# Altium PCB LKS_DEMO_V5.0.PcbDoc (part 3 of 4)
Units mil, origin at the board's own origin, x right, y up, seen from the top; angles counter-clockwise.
Board outline 5414.8 x 3354.56 mil, 2 copper layers (Top Layer, Bottom Layer); 131 components, 85 nets, 355 pads, 272 vias.
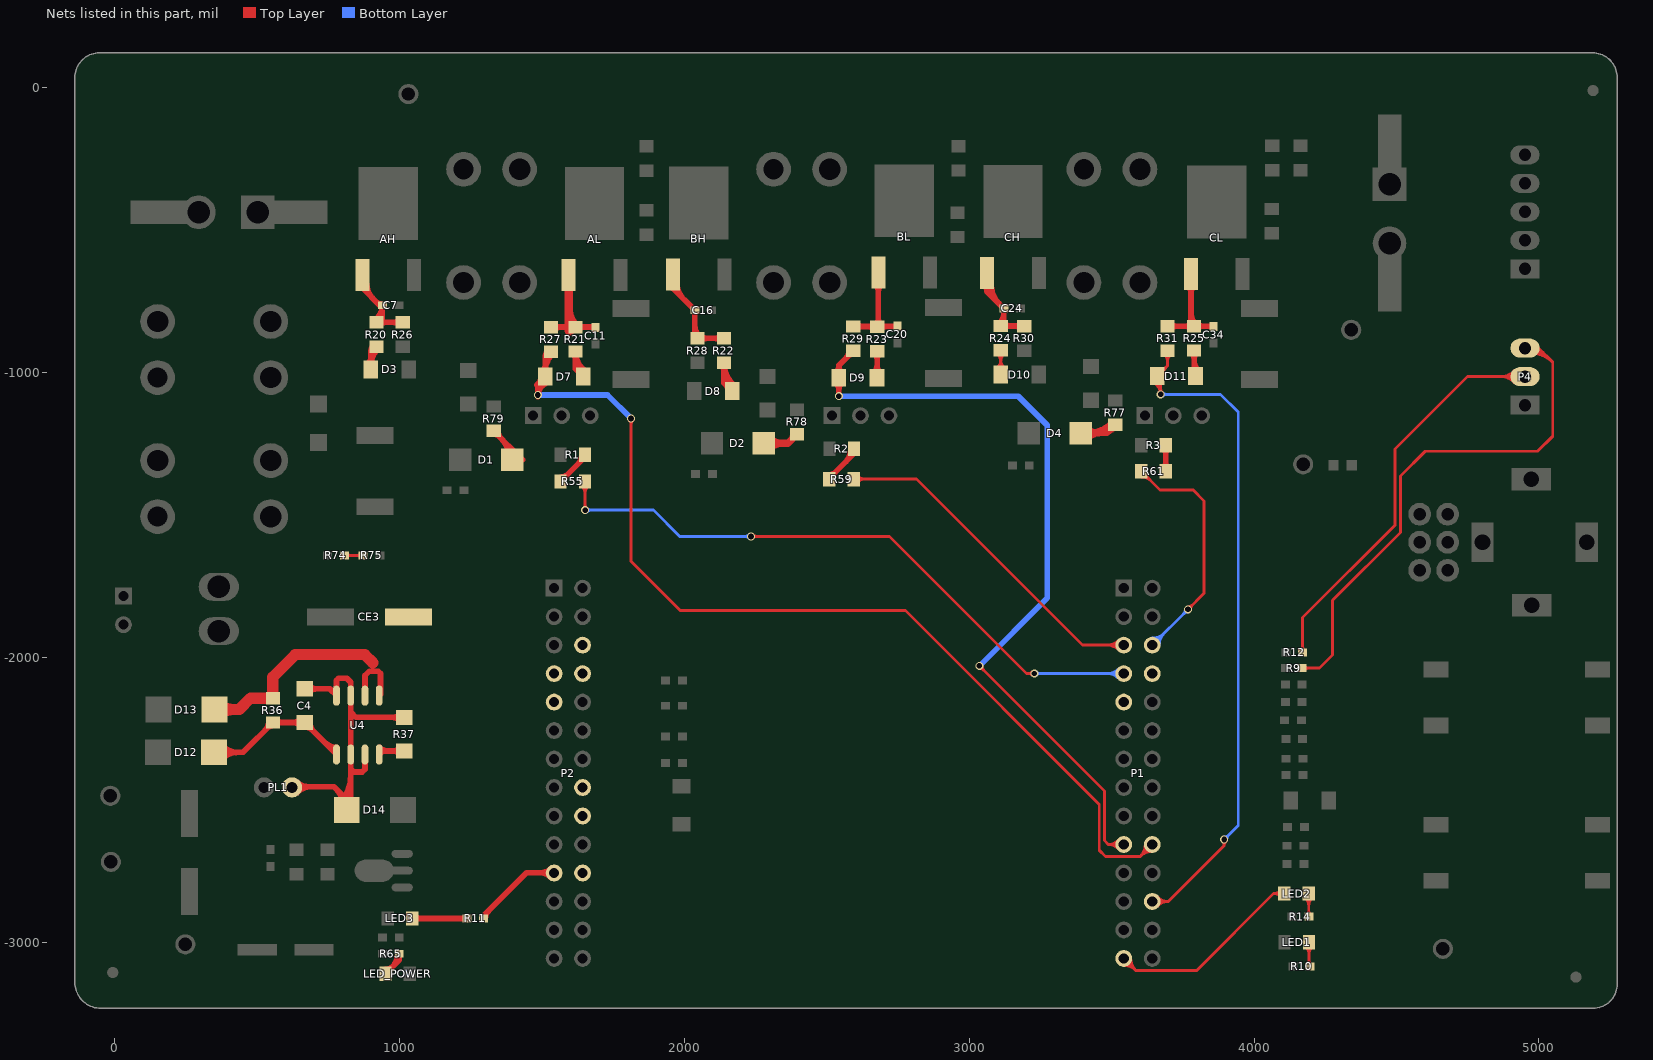
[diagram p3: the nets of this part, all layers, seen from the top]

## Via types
v1: diameter 26, hole 18, Top Layer to Bottom Layer, 117 vias
v2: diameter 28, hole 20, Top Layer to Bottom Layer, 77 vias
v3: diameter 28, hole 18, Top Layer to Bottom Layer, 73 vias
v4: diameter 23.62, hole 11.81, Top Layer to Bottom Layer, 5 vias

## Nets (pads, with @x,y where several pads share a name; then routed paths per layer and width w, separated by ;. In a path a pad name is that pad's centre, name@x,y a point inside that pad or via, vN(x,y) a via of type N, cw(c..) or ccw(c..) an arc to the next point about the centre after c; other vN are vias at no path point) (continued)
LED2: LED2.1 P1.14 | length 1103.3
  Top Layer w10: P1.14@3542.25,-3056.82 3584.65,-3099.22 3798.25,-3099.22 4068.35,-2829.12 ; LED2.1@4105.98,-2829.12 4068.35,-2829.12 ; 3567.05,-3081.62 ccw(c3542.25,-3106.42) 3542.25,-3071.34 cw(c3542.25,-3106.42) 3567.05,-3081.62 ; 3567.05,-3081.62 cw(c3591.85,-3056.82) 3556.78,-3056.82 ccw(c3591.85,-3056.82) 3567.05,-3081.62 ; 3584.12,-3098.69 ccw(c3542.25,-3140.56) 3542.25,-3081.34 cw(c3542.25,-3140.56) 3584.12,-3098.69 ; 3584.12,-3098.69 cw(c3625.99,-3056.82) 3566.78,-3056.82 ccw(c3625.99,-3056.82) 3584.12,-3098.69 ; 4068.35,-2829.12 ccw(c4068.35,-2794.93) 4093.65,-2817.92 cw(c4068.35,-2794.93) 4068.35,-2829.12 ; 4068.35,-2829.12 cw(c4068.35,-2863.3) 4093.65,-2840.31 ccw(c4068.35,-2863.3) 4068.35,-2829.12
LED3: P2.11 R11.2 | length 526.2
  Top Layer w20: R11.2@1295.18,-2916.6 1295.18,-2906.6 1446.24,-2755.53 P2.11@1540.97,-2755.53 ; R11.2@1300.93,-2916.6 cw(c1338.95,-2916.6) 1312.06,-2889.71 ccw(c1338.95,-2916.6) R11.2@1300.93,-2916.6 ; 1492.01,-2755.53 cw(c1492.01,-2807.06) 1528.44,-2770.62 ccw(c1492.01,-2807.06) 1492.01,-2755.53 ; 1498.2,-2755.53 ccw(c1498.2,-2712.77) 1528.44,-2743.01 cw(c1498.2,-2712.77) 1498.2,-2755.53
LO1: D11.2 P1.26 R31.1 | length 3359.8
  Top Layer w10: P1.26@3642.25,-2856.82 3698.24,-2856.82 ; v2(3671.64,-1076.41) 3671.63,-1023.64 D11.2@3660.13,-1012.14 3696.16,-976.11 ; R31.1@3696.16,-923.03 3696.16,-976.11 ; v2(3894.93,-2639.57) 3894.93,-2660.12 ; 3671.63,-1054.66 ccw(c3693.39,-1054.66) 3678,-1070.04 cw(c3693.39,-1054.66) 3671.63,-1054.66 ; 3671.63,-1054.7 cw(c3649.93,-1054.7) 3665.28,-1070.04 ccw(c3649.93,-1054.7) 3671.63,-1054.7 ; 3675.41,-2856.82 ccw(c3675.41,-2887.4) 3652.93,-2866.66 cw(c3675.41,-2887.4) 3675.41,-2856.82 ; 3675.41,-2856.82 cw(c3675.41,-2826.23) 3652.93,-2846.97 ccw(c3675.41,-2826.23) 3675.41,-2856.82 ; 3696.16,-976.11 cw(c3670.73,-950.68) 3663.99,-986.01 ccw(c3670.73,-950.68) 3696.16,-976.11 ; 3696.16,-963.23 ccw(c3655.95,-963.23) 3684.38,-934.8 cw(c3655.95,-963.23) 3696.16,-963.23 ; 3696.16,-963.23 cw(c3736.37,-963.23) 3707.94,-934.8 ccw(c3736.37,-963.23) 3696.16,-963.23 ; 3698.24,-2856.82 ccw(c3698.24,-2908.45) 3660.28,-2873.44 cw(c3698.24,-2908.45) 3698.24,-2856.82 ; 3698.24,-2856.82 cw(c3698.24,-2805.18) 3660.28,-2840.19 ccw(c3698.24,-2805.18) 3698.24,-2856.82 ; 3698.24,-2856.82 3894.93,-2660.12 ; 3894.93,-2660.12 ccw(c3875.97,-2660.12) 3888.83,-2646.19 cw(c3875.97,-2660.12) 3894.93,-2660.12 ; 3894.93,-2660.12 cw(c3913.89,-2660.12) 3901.03,-2646.19 ccw(c3913.89,-2660.12) 3894.93,-2660.12 ; D11.2@3648.83,-1035.25 cw(c3621.06,-1077.52) 3671.63,-1077.52 ccw(c3621.06,-1077.52) D11.2@3648.83,-1035.25 ; D11.2@3654.32,-1026.9 cw(c3633.24,-1058.99) 3671.63,-1058.99 ccw(c3633.24,-1058.99) D11.2@3654.32,-1026.9 ; D11.2@3662.12,-995.83 ccw(c3666.45,-973.11) 3682.8,-989.47 cw(c3666.45,-973.11) D11.2@3662.12,-995.83 ; D11.2@3680.72,-1006.23 cw(c3716.17,-1006.23) 3691.11,-981.16 ccw(c3716.17,-1006.23) D11.2@3680.72,-1006.23
  Bottom Layer w10: v2(3671.64,-1076.41) 3882.12,-1076.41 3944.39,-1138.68 3944.39,-2590.11 v2(3894.93,-2639.57) ; 3693.37,-1076.41 ccw(c3693.37,-1098.14) 3678,-1082.77 cw(c3693.37,-1098.14) 3693.37,-1076.41 ; 3693.37,-1076.41 cw(c3693.37,-1054.68) 3678,-1070.04 ccw(c3693.37,-1054.68) 3693.37,-1076.41 ; 3910.29,-2624.21 ccw(c3925.66,-2639.57) 3903.93,-2639.57 cw(c3925.66,-2639.57) 3910.29,-2624.21 ; 3910.29,-2624.21 cw(c3894.93,-2608.85) 3894.93,-2630.57 ccw(c3894.93,-2608.85) 3910.29,-2624.21
LO2: D9.2 P1.10 R29.1 | length 3418.4
  Top Layer w10: v2(3035.34,-2029.67) 3474.16,-2468.49 3474.16,-2643.33 3487.65,-2656.82 ; P1.10@3542.25,-2656.82 3487.65,-2656.82 ; 3050.71,-2045.04 ccw(c3035.34,-2060.4) 3035.34,-2038.67 cw(c3035.34,-2060.4) 3050.71,-2045.04 ; 3050.71,-2045.04 cw(c3066.07,-2029.67) 3044.34,-2029.67 ccw(c3066.07,-2029.67) 3050.71,-2045.04 ; 3487.65,-2656.82 ccw(c3487.65,-2608.31) 3523.91,-2640.53 cw(c3487.65,-2608.31) 3487.65,-2656.82 ; 3487.65,-2656.82 cw(c3487.65,-2705.32) 3523.91,-2673.11 ccw(c3487.65,-2705.32) 3487.65,-2656.82 ; 3509.91,-2656.82 ccw(c3509.91,-2628.09) 3531.39,-2647.17 cw(c3509.91,-2628.09) 3509.91,-2656.82 ; 3509.91,-2656.82 cw(c3509.91,-2685.55) 3531.39,-2666.46 ccw(c3509.91,-2685.55) 3509.91,-2656.82
  Top Layer w20: v2@2542,-1080.2 D9.2@2542,-1018.22 2542,-974.29 R29.1@2592.71,-923.58 ; 2542,-1061.76 ccw(c2504.36,-1061.76) 2530.98,-1035.15 cw(c2504.36,-1061.76) 2542,-1061.76 ; 2542,-1061.76 cw(c2579.64,-1061.76) 2553.03,-1035.15 ccw(c2579.64,-1061.76) 2542,-1061.76 ; 2542,-974.67 ccw(c2579.64,-974.67) 2553.03,-1001.29 cw(c2579.64,-974.67) 2542,-974.67 ; 2542,-974.67 cw(c2504.36,-974.67) 2530.98,-1001.29 ccw(c2504.36,-974.67) 2542,-974.67 ; 2567.1,-949.19 ccw(c2541.5,-923.58) 2577.71,-923.58 cw(c2541.5,-923.58) 2567.1,-949.19 ; R29.1@2575.18,-941.11 cw(c2589.36,-955.29) 2589.36,-935.24 ccw(c2589.36,-955.29) R29.1@2575.18,-941.11
  Bottom Layer w20: v2(2541.86,-1082.8) 3171.74,-1082.8 3273.63,-1184.7 3273.63,-1791.37 v2(3035.34,-2029.67)
LO3: D7.2 P1.24 R27.1 | length 4384.4
  Top Layer w10: v2(1812.37,-1160.96) 1812.37,-1662.33 1985.23,-1835.2 2775.6,-1835.2 3456.28,-2515.88 3456.28,-2677.23 3478.27,-2699.22 3599.85,-2699.22 P1.24@3638.22,-2660.84 ; 1812.37,-1182.68 ccw(c1790.64,-1182.68) 1806,-1167.32 cw(c1790.64,-1182.68) 1812.37,-1182.68 ; 1812.37,-1182.68 cw(c1834.1,-1182.68) 1818.73,-1167.32 ccw(c1834.1,-1182.68) 1812.37,-1182.68 ; 3600.38,-2698.69 ccw(c3558.51,-2656.82) 3617.72,-2656.82 cw(c3558.51,-2656.82) 3600.38,-2698.69 ; 3600.38,-2698.69 cw(c3642.25,-2740.56) 3642.25,-2681.34 ccw(c3642.25,-2740.56) 3600.38,-2698.69 ; 3617.45,-2681.62 ccw(c3592.65,-2656.82) 3627.72,-2656.82 cw(c3592.65,-2656.82) 3617.45,-2681.62 ; 3617.45,-2681.62 cw(c3642.25,-2706.42) 3642.25,-2671.34 ccw(c3642.25,-2706.42) 3617.45,-2681.62
  Top Layer w20: v2(1485.26,-1078.73) 1485.25,-1040.35 D7.2@1511.3,-1014.31 1511.3,-946.61 R27.1@1531.29,-926.62 ; 1511.29,-970.77 ccw(c1548.93,-970.77) 1522.32,-997.38 cw(c1548.93,-970.77) 1511.29,-970.77 ; 1511.3,-970.77 cw(c1473.66,-970.77) 1500.27,-997.38 ccw(c1473.66,-970.77) 1511.3,-970.77 ; 1482.3,-1043.31 cw(c1502.52,-1063.53) 1508.2,-1035.5 ccw(c1502.52,-1063.53) 1482.3,-1043.31 ; v2@1485.25,-1084.26 cw(c1539.73,-1084.26) 1517.62,-1034.47 ccw(c1539.73,-1084.26) v2@1485.25,-1084.26 ; 1485.25,-1053.49 cw(c1526.07,-1053.49) 1509.51,-1016.19 ccw(c1526.07,-1053.49) 1485.25,-1053.49 ; D7.2@1488.86,-1036.75 ccw(c1472.32,-1020.22) 1495.7,-1020.22 cw(c1472.32,-1020.22) D7.2@1488.86,-1036.75 ; D7.2@1511.29,-994.94 cw(c1596.27,-994.94) 1536.18,-934.86 ccw(c1596.27,-994.94) D7.2@1511.29,-994.94 ; R27.1@1511.3,-946.66 cw(c1547.99,-946.66) 1522.04,-920.71 ccw(c1547.99,-946.66) R27.1@1511.3,-946.66
  Bottom Layer w20: v2(1485.26,-1078.73) 1729.95,-1078.73 v2@1811.08,-1159.86
NetAH_1: AH.1 C7.1 R20.1 R26.2 | length 811.3
  Top Layer w20: AH.1@869.01,-654.65 869.01,-702.97 929.44,-763.4 C7.1@939.25,-763.4 ; R26.2@1010.36,-823.64 R20.1@918.27,-823.64 939.25,-802.67 C7.1@939.25,-763.4 ; C7.1@939.25,-763.4 cw(c874.31,-763.41) 914.42,-814.48 ccw(c874.31,-763.41) C7.1@939.25,-763.4 ; 949.75,-823.64 ccw(c949.75,-851.78) 929.86,-831.89 cw(c949.75,-851.78) 949.75,-823.64 ; 949.75,-823.64 cw(c949.75,-795.51) 929.86,-815.4 ccw(c949.75,-795.51) 949.75,-823.64 ; AH.1@884.52,-689.66 ccw(c954.1,-689.66) 904.9,-738.86 cw(c954.1,-689.66) AH.1@884.52,-689.66 ; 917.45,-751.41 ccw(c937.28,-731.58) 937.28,-759.63 cw(c937.28,-731.58) 917.45,-751.41 ; R20.1@926.77,-830.21 ccw(c906.62,-804.55) 939.25,-804.55 cw(c906.62,-804.55) R20.1@926.77,-830.21 ; 978.65,-823.64 cw(c978.65,-852.32) 998.93,-832.04 ccw(c978.65,-852.32) 978.65,-823.64 ; 979.42,-823.64 ccw(c979.42,-796.05) 998.93,-815.56 cw(c979.42,-796.05) 979.42,-823.64
NetAL_1: AL.1 C11.1 R21.1 R27.2 | length 760.3
  Top Layer w20: R27.2@1527.25,-839.83 C11.1@1687.64,-839.83 ; R27.2@1542.88,-849.23 cw(c1565.56,-871.91) 1565.56,-839.83 ccw(c1565.56,-871.91) R27.2@1542.88,-849.23 ; R27.2@1542.88,-832.75 ccw(c1559.98,-815.64) 1559.98,-839.83 cw(c1559.98,-815.64) R27.2@1542.88,-832.75 ; 1583.7,-839.83 cw(c1583.7,-870.45) 1605.36,-848.8 ccw(c1583.7,-870.45) 1583.7,-839.83 ; 1587.22,-839.83 ccw(c1587.22,-814.19) 1605.36,-832.32 cw(c1587.22,-814.19) 1587.22,-839.83 ; R21.1@1628.53,-848.8 cw(c1650.18,-870.45) 1650.18,-839.83 ccw(c1650.18,-870.45) R21.1@1628.53,-848.8 ; R21.1@1628.53,-832.32 ccw(c1646.66,-814.19) 1646.66,-839.83 cw(c1646.66,-814.19) R21.1@1628.53,-832.32
  Top Layer w30: R21.1@1593.54,-840.56 AL.1@1593.54,-657.72 ; R21.1@1593.54,-848.49 ccw(c1605.66,-848.49) 1597.09,-857.07 cw(c1605.66,-848.49) R21.1@1593.54,-848.49 ; 1593.54,-776.07 ccw(c1678.09,-776.07) 1618.3,-835.86 cw(c1678.09,-776.07) 1593.54,-776.07
NetBH_1: BH.1 C16.1 R22.1 R28.2 | length 714.4
  Top Layer w20: BH.1@1959.82,-653.06 1959.82,-704.49 C16.1@2036.35,-781.02 R28.2@2036.35,-870 ; R28.2@2046.11,-879.76 R22.1@2138.49,-879.76 ; 2077.59,-879.76 ccw(c2077.59,-907.89) 2057.69,-888 cw(c2077.59,-907.89) 2077.59,-879.76 ; 2077.59,-879.76 cw(c2077.59,-851.62) 2057.69,-871.52 ccw(c2077.59,-851.62) 2077.59,-879.76 ; BH.1@1974.12,-687.65 ccw(c2049.28,-687.65) 1996.13,-740.8 cw(c2049.28,-687.65) BH.1@1974.12,-687.65 ; 2036.35,-836.15 ccw(c2086.37,-836.15) 2051,-871.52 cw(c2086.37,-836.15) 2036.35,-836.15 ; 2106.85,-879.76 cw(c2106.85,-908.29) 2127.02,-888.11 ccw(c2106.85,-908.29) 2106.85,-879.76 ; 2107.41,-879.76 ccw(c2107.41,-852.02) 2127.02,-871.63 cw(c2107.41,-852.02) 2107.41,-879.76
NetBL_1: BL.1 C20.1 R23.1 R29.2 | length 803.9
  Top Layer w20: R29.2@2592.71,-837.95 C20.1@2745.87,-837.95 ; R23.1@2680.58,-835.25 BL.1@2680.58,-648.88 ; 2624.19,-837.95 ccw(c2624.19,-866.09) 2604.3,-846.2 cw(c2624.19,-866.09) 2624.19,-837.95 ; 2624.19,-837.95 cw(c2624.19,-809.82) 2604.3,-829.71 ccw(c2624.19,-809.82) 2624.19,-837.95 ; 2680.58,-715.64 ccw(c2645.32,-715.64) 2670.26,-690.7 cw(c2645.32,-715.64) 2680.58,-715.64 ; 2680.58,-715.64 cw(c2715.85,-715.64) 2690.91,-690.7 ccw(c2715.85,-715.64) 2680.58,-715.64 ; R23.1@2687.91,-831.27 ccw(c2704.06,-815.13) 2704.06,-837.95 cw(c2704.06,-815.13) R23.1@2687.91,-831.27 ; R23.1@2687.91,-831.27 cw(c2705.61,-813.57) 2680.58,-813.57 ccw(c2705.61,-813.57) R23.1@2687.91,-831.27 ; 2641.1,-837.95 cw(c2641.1,-871.39) 2664.74,-847.75 ccw(c2641.1,-871.39) 2641.1,-837.95 ; 2648.6,-837.95 ccw(c2648.6,-815.13) 2664.74,-831.27 cw(c2648.6,-815.13) 2648.6,-837.95 ; R23.1@2671.43,-831.27 ccw(c2649.34,-809.18) 2680.58,-809.18 cw(c2649.34,-809.18) R23.1@2671.43,-831.27 ; R23.1@2687.91,-847.75 cw(c2711.56,-871.39) 2711.56,-837.95 ccw(c2711.56,-871.39) R23.1@2687.91,-847.75
NetC24_1: C24.1 CH.1 R24.1 R30.2 | length 904.2
  Top Layer w20: CH.1@3061.3,-663.73 3061.3,-714.91 ; R24.1@3110.16,-836.37 R24.1@3121.14,-836.37 ; R24.1@3121.14,-839.76 R24.1@3121.14,-836.37 ; R30.2@3192.03,-836.37 R24.1@3121.14,-836.37 ; 3061.3,-714.95 cw(c3088.02,-714.95) 3071.7,-693.79 ccw(c3088.02,-714.95) 3061.3,-714.95 ; 3061.3,-714.91 C24.1@3121.14,-774.76 R24.1@3121.14,-836.37 ; 3141.64,-836.37 ccw(c3141.64,-864.5) 3121.75,-844.61 cw(c3141.64,-864.5) 3141.64,-836.37 ; 3141.64,-836.37 cw(c3141.64,-808.23) 3121.75,-828.13 ccw(c3141.64,-808.23) 3141.64,-836.37 ; CH.1@3052.45,-692.55 cw(c3031.1,-713.9) 3061.3,-713.9 ccw(c3031.1,-713.9) CH.1@3052.45,-692.55 ; CH.1@3057.41,-681.72 ccw(c3114.47,-687.04) 3073.95,-727.56 cw(c3114.47,-687.04) CH.1@3057.41,-681.72 ; CH.1@3077.32,-683.58 ccw(c3169.54,-692.18) 3104.05,-757.66 cw(c3169.54,-692.18) CH.1@3077.32,-683.58 ; R24.1@3105.27,-828.13 ccw(c3066.95,-789.81) 3121.14,-789.81 cw(c3066.95,-789.81) R24.1@3105.27,-828.13 ; 3159.27,-836.37 cw(c3159.27,-867.6) 3181.35,-845.52 ccw(c3159.27,-867.6) 3159.27,-836.37 ; 3163.65,-836.37 ccw(c3163.65,-811.34) 3181.35,-829.04 cw(c3163.65,-811.34) 3163.65,-836.37
NetC34_1: C34.1 CL.1 R25.1 R31.2 | length 818
  Top Layer w20: R31.2@3696.16,-837.4 R25.1@3778.11,-837.4 ; R25.1@3778.11,-837.99 R25.1@3778.11,-837.4 ; CL.1@3778.11,-642.68 R25.1@3778.11,-837.4 ; C34.1@3857.48,-837.4 R25.1@3778.11,-837.4 ; 3727.64,-837.4 ccw(c3727.64,-865.53) 3707.75,-845.64 cw(c3727.64,-865.53) 3727.64,-837.4 ; 3727.64,-837.4 cw(c3727.64,-809.26) 3707.75,-829.16 ccw(c3727.64,-809.26) 3727.64,-837.4 ; 3757.05,-837.4 ccw(c3757.05,-808.4) 3777.56,-828.9 cw(c3757.05,-808.4) 3757.05,-837.4 ; 3758.28,-837.4 cw(c3758.28,-864.67) 3777.56,-845.39 ccw(c3758.28,-864.67) 3758.28,-837.4 ; CL.1@3768.16,-695.16 cw(c3744.14,-719.18) 3778.11,-719.18 ccw(c3744.14,-719.18) CL.1@3768.16,-695.16 ; 3778.11,-790.45 ccw(c3832.5,-790.45) 3794.04,-828.9 cw(c3832.5,-790.45) 3778.11,-790.45 ; 3778.11,-721.01 cw(c3814.67,-721.01) 3788.82,-695.16 ccw(c3814.67,-721.01) 3778.11,-721.01 ; R25.1@3800.73,-845.39 cw(c3820.02,-864.67) 3820.02,-837.4 ccw(c3820.02,-864.67) R25.1@3800.73,-845.39 ; R25.1@3800.73,-828.9 ccw(c3821.24,-808.4) 3821.24,-837.4 cw(c3821.24,-808.4) R25.1@3800.73,-828.9
NetCF1_1: CE3.1 D13.2 R36.2 U4.5 U4.6 | length 1127.5
  Top Layer w20: U4.6@878.24,-2134.07 878.24,-2063.8 893.82,-2048.21 924.43,-2048.21 932.49,-2056.26 932.49,-2129.81 U4.5@928.24,-2134.07 ; U4.5@926.82,-2109.22 ccw(c913.14,-2095.54) 932.49,-2095.54 cw(c913.14,-2095.54) U4.5@926.82,-2109.22
  Top Layer w40: D13.2@350,-2182.97 436.59,-2182.97 476.64,-2142.91 R36.2@554.9,-2142.91 554.9,-2068.88 634.08,-1989.7 876.84,-1989.7 906.05,-2018.91 ; 411.02,-2182.97 ccw(c411.02,-2243.99) 367.87,-2200.84 cw(c411.02,-2243.99) 411.02,-2182.97 ; 411.02,-2182.97 cw(c411.02,-2121.95) 367.87,-2165.09 ccw(c411.02,-2121.95) 411.02,-2182.97
NetCF2_1: C4.1 D12.2 R36.1 U4.1 | length 1323.8
  Top Layer w20: D12.2@348.55,-2333.06 450.38,-2333.06 R36.1@554.9,-2228.54 555.19,-2228.25 C4.1@666.53,-2228.25 U4.1@778.24,-2339.96 ; 433.72,-2333.06 ccw(c433.72,-2418.23) 373.5,-2358.01 cw(c433.72,-2418.23) 433.72,-2333.06 ; 433.72,-2333.06 cw(c433.72,-2247.9) 373.5,-2308.12 ccw(c433.72,-2247.9) 433.72,-2333.06 ; 624.54,-2228.25 ccw(c624.54,-2188.24) 652.84,-2216.53 cw(c624.54,-2188.24) 624.54,-2228.25 ; 624.54,-2228.25 cw(c624.54,-2268.27) 652.84,-2239.97 ccw(c624.54,-2268.27) 624.54,-2228.25 ; 529.3,-2254.15 ccw(c503.69,-2228.54) 539.9,-2228.54 cw(c503.69,-2228.54) 529.3,-2254.15 ; R36.1@537.38,-2246.07 cw(c551.56,-2260.25) 551.56,-2240.19 ccw(c551.56,-2260.25) R36.1@537.38,-2246.07 ; R36.1@566.49,-2236.78 cw(c587.07,-2257.36) 587.07,-2228.25 ccw(c587.07,-2257.36) R36.1@566.49,-2236.78 ; R36.1@566.49,-2220.3 ccw(c585.7,-2201.09) 585.7,-2228.25 cw(c585.7,-2201.09) R36.1@566.49,-2220.3 ; C4.1@668.5,-2244.83 cw(c668.5,-2280.09) 693.43,-2255.16 ccw(c668.5,-2280.09) C4.1@668.5,-2244.83 ; C4.1@685.07,-2228.25 ccw(c729.84,-2228.25) 698.18,-2259.91 cw(c729.84,-2228.25) C4.1@685.07,-2228.25 ; 736.7,-2298.43 ccw(c778.24,-2256.89) 778.24,-2315.63 cw(c778.24,-2256.89) 736.7,-2298.43 ; U4.1@770.84,-2332.57 ccw(c778.24,-2325.18) 778.24,-2335.63 cw(c778.24,-2325.18) U4.1@770.84,-2332.57
NetCF2_2: C4.2 D14.2 PL1.2 R37.2 U4.2 U4.3 U4.7 U4.8 | length 2328.9
  Top Layer w20: PL1.2@622.13,-2453.71 768.46,-2453.71 D14.2@814.33,-2499.58 ; C4.2@666.53,-2110.14 754.32,-2110.14 U4.8@778.24,-2134.07 778.24,-2081 785.96,-2073.27 814.08,-2073.27 828.24,-2087.43 828.24,-2510.27 D14.2@814.33,-2524.18 ; D14.2@814.33,-2535.22 D14.2@814.33,-2496.56 ; 828.24,-2391.62 838.97,-2402.35 868.32,-2402.35 878.24,-2392.44 U4.3@878.24,-2341.07 ; 828.24,-2191.87 846.94,-2210.57 R37.2@1016.47,-2210.57 ; 708.51,-2110.14 ccw(c708.51,-2150.16) 680.22,-2121.86 cw(c708.51,-2150.16) 708.51,-2110.14 ; 708.51,-2110.14 cw(c708.51,-2070.13) 680.22,-2098.42 ccw(c708.51,-2070.13) 708.51,-2110.14 ; 974.49,-2210.57 ccw(c974.49,-2170.55) 1002.79,-2198.85 cw(c974.49,-2170.55) 974.49,-2210.57 ; 974.49,-2210.57 cw(c974.49,-2250.58) 1002.79,-2222.29 ccw(c974.49,-2250.58) 974.49,-2210.57 ; PL1.2@640.11,-2474.41 cw(c690.08,-2524.37) 690.08,-2453.71 ccw(c690.08,-2524.37) PL1.2@640.11,-2474.41 ; PL1.2@640.11,-2438.44 ccw(c676.98,-2401.57) 676.98,-2453.71 cw(c676.98,-2401.57) PL1.2@640.11,-2438.44 ; 777.6,-2462.85 cw(c722.1,-2518.34) 799.3,-2532.47 ccw(c722.1,-2518.34) 777.6,-2462.85 ; D14.2@789.38,-2510.28 ccw(c695.59,-2416.48) 828.24,-2416.48 cw(c695.59,-2416.48) D14.2@789.38,-2510.28 ; D14.2@803.53,-2524.42 ccw(c743.87,-2464.76) 828.24,-2464.76 cw(c743.87,-2464.76) D14.2@803.53,-2524.42 ; 804.55,-2489.8 cw(c767.67,-2526.68) 818.98,-2536.07 ccw(c767.67,-2526.68) 804.55,-2489.8 ; 828.24,-2483.64 ccw(c865.91,-2483.64) 839.27,-2510.28 cw(c865.91,-2483.64) 828.24,-2483.64
NetD1_2: D1.2 R79.2 | length 498.1
  Top Layer w20: R79.2@1329.96,-1204.56 D1.2@1431.45,-1306.06 ; R79.2@1333.31,-1216.22 cw(c1333.31,-1236.27) 1347.49,-1222.09 ccw(c1333.31,-1236.27) R79.2@1333.31,-1216.22 ; R79.2@1344.96,-1204.56 ccw(c1381.17,-1204.56) 1355.57,-1230.17 cw(c1381.17,-1204.56) R79.2@1344.96,-1204.56 ; 1354.15,-1228.75 cw(c1277.16,-1305.74) 1386.04,-1305.74 ccw(c1277.16,-1305.74) 1354.15,-1228.75 ; 1388.29,-1262.9 cw(c1345.45,-1305.74) 1406.04,-1305.74 ccw(c1345.45,-1305.74) 1388.29,-1262.9
NetD2_2: D2.2 R78.2 | length 381.2
  Top Layer w25: D2.2@2278.58,-1248.27 2363.15,-1248.27 R78.2@2395.27,-1216.16 ; 2343.45,-1248.28 ccw(c2343.45,-1313.15) 2297.58,-1267.28 cw(c2343.45,-1313.15) 2343.45,-1248.28 ; 2343.45,-1248.27 cw(c2343.45,-1183.4) 2297.58,-1229.27 ccw(c2343.45,-1183.4) 2343.45,-1248.27 ; R78.2@2373.93,-1237.5 ccw(c2352.59,-1216.16) 2382.77,-1216.16 cw(c2352.59,-1216.16) R78.2@2373.93,-1237.5
NetD3_1: D3.1 R20.2 | length 394.2
  Top Layer w20: D3.1@898.55,-988.88 898.55,-929 R20.2@918.27,-909.27 ; 898.55,-945.33 ccw(c936.19,-945.33) 909.57,-971.95 cw(c936.19,-945.33) 898.55,-945.33 ; 898.55,-945.33 cw(c860.91,-945.33) 887.52,-971.95 ccw(c860.91,-945.33) 898.55,-945.33 ; D3.1@898.55,-976.95 cw(c982.6,-976.95) 923.17,-917.52 ccw(c982.6,-976.95) D3.1@898.55,-976.95 ; R20.2@898.55,-928.66 cw(c934.31,-928.66) 909.02,-903.37 ccw(c934.31,-928.66) R20.2@898.55,-928.66
NetD4_2: D4.2 R77.2 | length 775.5
  Top Layer w20: D4.2@3391.45,-1213.21 3482.43,-1213.21 R77.2@3512.15,-1183.48 ; 3462.36,-1213.21 ccw(c3462.36,-1284.11) 3412.22,-1233.98 cw(c3462.36,-1284.11) 3462.36,-1213.21 ; 3462.36,-1213.21 cw(c3462.36,-1142.3) 3412.22,-1192.44 ccw(c3462.36,-1142.3) 3462.36,-1213.21 ; D4.2@3408.91,-1213.21 ccw(c3408.91,-1083.59) 3500.57,-1175.24 cw(c3408.91,-1083.59) D4.2@3408.91,-1213.21 ; 3457.2,-1213.21 ccw(c3457.2,-1131.88) 3514.71,-1189.39 cw(c3457.2,-1131.88) 3457.2,-1213.21 ; 3486.55,-1209.09 ccw(c3460.94,-1183.48) 3497.15,-1183.48 cw(c3460.94,-1183.48) 3486.55,-1209.09 ; R77.2@3494.63,-1201.01 cw(c3508.81,-1215.19) 3508.81,-1195.14 ccw(c3508.81,-1215.19) R77.2@3494.63,-1201.01
NetD7_1: D7.1 R21.2 | length 546
  Top Layer w20: D7.1@1645.15,-1014.31 1616.94,-986.1 R21.2@1616.94,-926.19 ; 1616.94,-954.32 ccw(c1588.81,-954.32) 1608.7,-934.43 cw(c1588.81,-954.32) 1616.94,-954.32 ; 1616.94,-954.32 cw(c1645.08,-954.32) 1625.18,-934.43 ccw(c1645.08,-954.32) 1616.94,-954.32 ; R21.2@1616.94,-926.19 ccw(c1700.41,-926.19) 1653.85,-995.47 cw(c1700.41,-926.19) R21.2@1616.94,-926.19 ; 1616.94,-963.73 ccw(c1675.18,-963.73) 1642.69,-1012.07 cw(c1675.18,-963.73) 1616.94,-963.73 ; D7.1@1619.9,-989.06 ccw(c1633.66,-975.3) 1640.04,-993.68 cw(c1633.66,-975.3) D7.1@1619.9,-989.06 ; D7.1@1622.71,-991.87 cw(c1606.18,-1008.41) 1629.56,-1008.41 ccw(c1606.18,-1008.41) D7.1@1622.71,-991.87
NetD8_1: D8.1 R22.2 | length 597.7
  Top Layer w20: R22.2@2138.61,-965.5 2138.61,-1036.36 D8.1@2167.67,-1065.43 ; 2138.61,-993.64 ccw(c2110.47,-993.64) 2130.37,-973.74 cw(c2110.47,-993.64) 2138.61,-993.64 ; 2138.61,-993.64 cw(c2166.74,-993.64) 2146.85,-973.74 ccw(c2166.74,-993.64) 2138.61,-993.64 ; 2138.61,-1007.62 ccw(c2209.99,-1007.62) 2164.88,-1062.94 cw(c2209.99,-1007.62) 2138.61,-1007.62 ; R22.2@2138.61,-965.5 ccw(c2244.32,-965.51) 2177.52,-1047.44 cw(c2244.32,-965.51) R22.2@2138.61,-965.5 ; 2141.56,-1039.32 ccw(c2156.71,-1024.17) 2163.05,-1044.63 cw(c2156.71,-1024.17) 2141.56,-1039.32 ; D8.1@2145.23,-1042.99 cw(c2128.7,-1059.52) 2152.08,-1059.52 ccw(c2128.7,-1059.52) D8.1@2145.23,-1042.99
NetD9_1: D9.1 R23.2 | length 299.2
  Top Layer w20: D9.1@2676.33,-1017.75 R23.2@2676.33,-925.14 ; 2676.33,-953.27 ccw(c2648.19,-953.27) 2668.09,-933.38 cw(c2648.19,-953.27) 2676.33,-953.27 ; 2676.33,-953.27 cw(c2704.46,-953.27) 2684.57,-933.38 ccw(c2704.46,-953.27) 2676.33,-953.27 ; D9.1@2664.83,-1001.29 ccw(c2637.09,-973.54) 2676.33,-973.54 cw(c2637.09,-973.54) D9.1@2664.83,-1001.29 ; 2676.33,-975.81 ccw(c2712.37,-975.81) 2686.88,-1001.29 cw(c2712.37,-975.81) 2676.33,-975.81
NetD10_1: D10.1 R24.2 | length 409.3
  Top Layer w10: D10.1@3110.16,-1007.24 R24.2@3110.16,-922 ; 3110.16,-962.2 ccw(c3069.96,-962.2) 3098.39,-933.77 cw(c3069.96,-962.2) 3110.16,-962.2 ; 3110.16,-962.2 cw(c3150.37,-962.2) 3121.94,-933.77 ccw(c3150.37,-962.2) 3110.16,-962.2 ; D10.1@3095.87,-987.04 ccw(c3061.37,-952.54) 3110.16,-952.54 cw(c3061.37,-952.54) D10.1@3095.87,-987.04 ; 3110.16,-975.39 ccw(c3136.64,-975.39) 3117.92,-994.12 cw(c3136.64,-975.39) 3110.16,-975.39 ; 3110.16,-951.25 ccw(c3160.79,-951.25) 3124.99,-987.04 cw(c3160.79,-951.25) 3110.16,-951.25
NetD11_1: D11.1 R25.2 | length 291.2
  Top Layer w20: D11.1@3789.15,-1007.3 R25.2@3789.15,-922.77 ; 3789.15,-950.91 ccw(c3761.01,-950.91) 3780.91,-931.02 cw(c3761.01,-950.91) 3789.15,-950.91 ; 3789.15,-950.91 cw(c3817.28,-950.91) 3797.39,-931.02 ccw(c3817.28,-950.91) 3789.15,-950.91 ; D11.1@3782.96,-995.21 ccw(c3768.04,-980.29) 3789.15,-980.29 cw(c3768.04,-980.29) D11.1@3782.96,-995.21 ; 3789.15,-956.9 ccw(c3843.32,-956.9) 3805.01,-995.21 cw(c3843.32,-956.9) 3789.15,-956.9
NetLED1_2: LED1.2 R10.1 | length 278.7
  Top Layer w10: LED1.2@4192.4,-3000.22 4192.4,-3081.09 R10.1@4195.91,-3084.6 ; 4192.4,-3043.77 ccw(c4152.2,-3043.77) 4180.62,-3015.34 cw(c4152.2,-3043.77) 4192.4,-3043.77 ; 4192.4,-3043.77 cw(c4232.61,-3043.77) 4204.18,-3015.34 ccw(c4232.61,-3043.77) 4192.4,-3043.77 ; R10.1@4187.73,-3078.39 ccw(c4176.46,-3067.12) 4192.4,-3067.12 cw(c4176.46,-3067.12) R10.1@4187.73,-3078.39 ; 4192.4,-3059.69 ccw(c4218.85,-3059.69) 4200.15,-3078.39 cw(c4218.85,-3059.69) 4192.4,-3059.69
NetLED2_2: LED2.2 R14.1 | length 273.2
  Top Layer w10: R14.1@4191.61,-2909.42 LED2.2@4191.61,-2829.12 ; 4191.61,-2872.67 ccw(c4151.4,-2872.67) 4179.83,-2844.24 cw(c4151.4,-2872.67) 4191.61,-2872.67 ; 4191.61,-2872.67 cw(c4231.81,-2872.67) 4203.38,-2844.24 ccw(c4231.81,-2872.67) 4191.61,-2872.67 ; R14.1@4185.79,-2903.61 ccw(c4171.76,-2889.57) 4191.61,-2889.57 cw(c4171.76,-2889.57) R14.1@4185.79,-2903.61 ; 4191.61,-2887.67 ccw(c4214.15,-2887.67) 4198.21,-2903.61 cw(c4214.15,-2887.67) 4191.61,-2887.67
NetLED3_1: LED3.1 R11.1 | length 278.1
  Top Layer w20: LED3.1@1043.88,-2916.56 R11.1@1233.59,-2916.56 ; 1072.01,-2916.56 ccw(c1072.01,-2944.69) 1052.12,-2924.8 cw(c1072.01,-2944.69) 1072.01,-2916.56 ; 1072.01,-2916.56 cw(c1072.01,-2888.42) 1052.12,-2908.32 ccw(c1072.01,-2888.42) 1072.01,-2916.56
NetLED_POWER_1: LED_POWER.1 R65.2 | length 284.3
  Top Layer w20: LED_POWER.1@950.38,-3110.82 998.63,-3062.57 R65.2@998.63,-3040.48 ; LED_POWER.1@950.38,-3095.82 ccw(c950.38,-3059.61) 975.99,-3085.21 cw(c950.38,-3059.61) LED_POWER.1@950.38,-3095.82 ; LED_POWER.1@962.03,-3107.47 cw(c982.09,-3107.47) 967.91,-3093.29 ccw(c982.09,-3107.47) LED_POWER.1@962.03,-3107.47 ; 973.2,-3088 ccw(c925.68,-3040.48) 992.88,-3040.48 cw(c925.68,-3040.48) 973.2,-3088
NetP13_2: P4.2 R12.1 | length 1833.7
  Top Layer w10: R12.1@4170.04,-1982.47 4170.04,-1860.24 4494.03,-1536.25 4494.03,-1268.84 4748.7,-1014.16 P4.2@4951.92,-1014.16 ; 4170.04,-1961.28 ccw(c4191.24,-1961.28) 4176.25,-1976.27 cw(c4191.24,-1961.28) 4170.04,-1961.28 ; 4170.04,-1961.28 cw(c4148.85,-1961.28) 4163.84,-1976.27 ccw(c4148.85,-1961.28) 4170.04,-1961.28 ; 4864.54,-1014.16 ccw(c4864.54,-945.44) 4913.13,-994.03 cw(c4864.54,-945.44) 4864.54,-1014.16 ; 4864.54,-1014.16 cw(c4864.54,-1082.88) 4913.13,-1034.29 ccw(c4864.54,-1082.88) 4864.54,-1014.16 ; 4888.69,-1014.16 ccw(c4888.69,-969.58) 4920.21,-1001.1 cw(c4888.69,-969.58) 4888.69,-1014.16 ; 4888.69,-1014.16 cw(c4888.69,-1058.74) 4920.21,-1027.22 ccw(c4888.69,-1058.74) 4888.69,-1014.16
NetP13_3: P4.3 R9.2 | length 2299.8
  Top Layer w10: R9.2@4168.67,-2037.33 4229.85,-2037.33 4275.27,-1991.91 4275.27,-1799.57 4513.64,-1561.2 4513.64,-1363.11 4600.6,-1276.15 4995.32,-1276.15 5048.21,-1223.26 5048.21,-963.84 4998.53,-914.16 P4.3@4950.98,-914.16 ; 4191.83,-2037.33 ccw(c4191.83,-2058.52) 4176.84,-2043.54 cw(c4191.83,-2058.52) 4191.83,-2037.33 ; 4191.83,-2037.33 cw(c4191.83,-2016.13) 4176.84,-2031.12 ccw(c4191.83,-2016.13) 4191.83,-2037.33 ; P4.3@4968.63,-912.63 cw(c4971.4,-974.22) 5015,-930.62 ccw(c4971.4,-974.22) P4.3@4968.63,-912.63 ; P4.3@4969.08,-922.62 cw(c4972.78,-1004.93) 5031.04,-946.67 ccw(c4972.78,-1004.93) P4.3@4969.08,-922.62 ; P4.3@4969.52,-932.61 cw(c4974.16,-1035.63) 5047.08,-962.71 ccw(c4974.16,-1035.63) P4.3@4969.52,-932.61
NetR1_1: R1.1 R55.2 | length 271.8
  Top Layer w20: R55.2@1564.85,-1382.3 R1.1@1650.48,-1296.67 ; R55.2@1564.85,-1367.3 ccw(c1564.85,-1331.09) 1590.46,-1356.69 cw(c1564.85,-1331.09) R55.2@1564.85,-1367.3 ; R55.2@1576.51,-1378.95 cw(c1596.56,-1378.95) 1582.38,-1364.77 ccw(c1596.56,-1378.95) R55.2@1576.51,-1378.95 ; 1627.21,-1319.94 ccw(c1599.16,-1291.89) 1638.83,-1291.89 cw(c1599.16,-1291.89) 1627.21,-1319.94
NetR2_1: R2.1 R59.2 | length 314.7
  Top Layer w20: R59.2@2512.6,-1366.52 2594.94,-1284.17 R2.1@2594.94,-1267.81 ; R59.2@2508.65,-1359.16 ccw(c2508.65,-1331.87) 2527.95,-1351.17 cw(c2508.65,-1331.87) R59.2@2508.65,-1359.16 ; R59.2@2520.3,-1370.81 cw(c2549.28,-1370.81) 2528.79,-1350.33 ccw(c2549.28,-1370.81) R59.2@2520.3,-1370.81 ; 2565.85,-1313.27 ccw(c2523.74,-1271.16) 2583.29,-1271.16 cw(c2523.74,-1271.16) 2565.85,-1313.27
NetR3_1: R3.1 R61.2 | length 267.6
  Top Layer w20: R61.2@3689.55,-1346.42 R3.1@3689.51,-1255.52 ; 3689.51,-1287 ccw(c3661.38,-1287) 3681.27,-1267.1 cw(c3661.38,-1287) 3689.51,-1287 ; 3689.51,-1287 cw(c3717.65,-1287) 3697.75,-1267.1 ccw(c3717.65,-1287) 3689.51,-1287 ; R61.2@3681.3,-1334.84 ccw(c3661.49,-1315.02) 3689.51,-1315.02 cw(c3661.49,-1315.02) R61.2@3681.3,-1334.84 ; 3689.51,-1314.87 ccw(c3717.75,-1314.87) 3697.79,-1334.84 cw(c3717.75,-1314.87) 3689.51,-1314.87
NetR74_2: R74.2 R75.1 | length 199.3
  Top Layer w10: R74.2@805.68,-1641.8 R75.1@871.84,-1641.8 ; 828.84,-1641.8 ccw(c828.84,-1663) 813.86,-1648.01 cw(c828.84,-1663) 828.84,-1641.8 ; 828.84,-1641.8 cw(c828.84,-1620.61) 813.86,-1635.6 ccw(c828.84,-1620.61) 828.84,-1641.8 ; 848.65,-1641.8 ccw(c848.65,-1620.58) 863.66,-1635.59 cw(c848.65,-1620.58) 848.65,-1641.8 ; 848.69,-1641.8 cw(c848.69,-1662.97) 863.66,-1648 ccw(c848.69,-1662.97) 848.69,-1641.8
NetRP2_1: R37.1 U4.4 | length 285.9
  Top Layer w20: U4.4@928.24,-2341.07 940.62,-2328.68 R37.1@1016.47,-2328.68 ; 974.49,-2328.68 ccw(c974.49,-2288.66) 1002.79,-2316.96 cw(c974.49,-2288.66) 974.49,-2328.68 ; 974.49,-2328.68 cw(c974.49,-2368.69) 1002.79,-2340.4 ccw(c974.49,-2368.69) 974.49,-2328.68 ; U4.4@929.65,-2316.22 ccw(c959.73,-2286.14) 959.73,-2328.68 cw(c959.73,-2286.14) U4.4@929.65,-2316.22
NRST: P2.23
OC: P2.4
P0.0: P2.22
P0.4: P2.25
P1.10: P1.5
P1.11: P1.18
P2.2: P2.18
P2.3: P2.5
P2.10: P2.17
PA: P1.4 R55.1 | length 3060.1
  Top Layer w10: v2@1650.48,-1482.37 R55.1@1650.48,-1382.3 ; v2(2233.4,-1575.15) 2719.74,-1575.14 3201.03,-2056.43 v3(3228,-2056.43) ; 1650.48,-1425.85 ccw(c1610.28,-1425.85) 1638.71,-1397.42 cw(c1610.28,-1425.85) 1650.48,-1425.85 ; 1650.48,-1425.85 cw(c1690.69,-1425.85) 1662.26,-1397.42 ccw(c1690.69,-1425.85) 1650.48,-1425.85 ; 3206.27,-2056.43 ccw(c3206.27,-2034.7) 3221.64,-2050.07 cw(c3206.27,-2034.7) 3206.27,-2056.43 ; 3206.27,-2056.43 cw(c3206.27,-2078.16) 3221.64,-2062.8 ccw(c3206.27,-2078.16) 3206.27,-2056.43 ; v2@1645.14,-1476.47 ccw(c1632.25,-1463.58) 1650.48,-1463.58 cw(c1632.25,-1463.58) v2@1645.14,-1476.47 ; 1650.48,-1458.63 ccw(c1675.71,-1458.63) 1657.87,-1476.47 cw(c1675.71,-1458.63) 1650.48,-1458.63 ; v2@2239.76,-1581.52 cw(c2255.15,-1596.9) 2255.15,-1575.14 ccw(c2255.15,-1596.9) v2@2239.76,-1581.52 ; v2@2239.76,-1568.79 ccw(c2255.1,-1553.45) 2255.1,-1575.14 cw(c2255.1,-1553.45) v2@2239.76,-1568.79
  Bottom Layer w10: v2(1651.51,-1482.83) 1890.86,-1482.83 1983.17,-1575.15 v2(2233.4,-1575.15) ; v3(3228,-2056.43) P1.4@3541.86,-2056.43 ; 1673.23,-1482.83 ccw(c1673.23,-1504.56) 1657.87,-1489.2 cw(c1673.23,-1504.56) 1673.23,-1482.83 ; 1673.23,-1482.83 cw(c1673.23,-1461.11) 1657.87,-1476.47 ccw(c1673.23,-1461.11) 1673.23,-1482.83 ; 2211.67,-1575.15 ccw(c2211.67,-1553.43) 2227.03,-1568.79 cw(c2211.67,-1553.43) 2211.67,-1575.15 ; 2211.67,-1575.15 cw(c2211.67,-1596.88) 2227.03,-1581.52 ccw(c2211.67,-1596.88) 2211.67,-1575.15 ; 3249.73,-2056.43 ccw(c3249.73,-2078.16) 3234.36,-2062.8 cw(c3249.73,-2078.16) 3249.73,-2056.43 ; 3249.73,-2056.43 cw(c3249.73,-2034.7) 3234.36,-2050.07 ccw(c3249.73,-2034.7) 3249.73,-2056.43 ; 3482.11,-2056.43 cw(c3482.11,-2116.96) 3524.91,-2074.16 ccw(c3482.11,-2116.96) 3482.11,-2056.43 ; 3483.96,-2056.43 ccw(c3483.96,-1998.53) 3524.91,-2039.47 cw(c3483.96,-1998.53) 3483.96,-2056.43 ; 3506.25,-2056.43 cw(c3506.25,-2092.82) 3531.98,-2067.09 ccw(c3506.25,-2092.82) 3506.25,-2056.43 ; 3508.1,-2056.43 ccw(c3508.1,-2022.67) 3531.98,-2046.54 cw(c3508.1,-2022.67) 3508.1,-2056.43
PB: P1.3 R59.1 | length 1611.8
  Top Layer w10: R59.1@2594.28,-1374.16 2814.25,-1374.16 3396.9,-1956.82 P1.3@3542.25,-1956.82 ; 2634.48,-1374.16 ccw(c2634.48,-1414.37) 2606.06,-1385.94 cw(c2634.48,-1414.37) 2634.48,-1374.16 ; 2634.48,-1374.16 cw(c2634.48,-1333.96) 2606.06,-1362.39 ccw(c2634.48,-1333.96) 2634.48,-1374.16 ; 3483.03,-1956.82 ccw(c3483.03,-1897.6) 3524.91,-1939.47 cw(c3483.03,-1897.6) 3483.03,-1956.82 ; 3483.03,-1956.82 cw(c3483.03,-2016.03) 3524.91,-1974.16 ccw(c3483.03,-2016.03) 3483.03,-1956.82 ; 3507.18,-1956.82 ccw(c3507.18,-1921.74) 3531.98,-1946.54 cw(c3507.18,-1921.74) 3507.18,-1956.82 ; 3507.18,-1956.82 cw(c3507.18,-1991.89) 3531.98,-1967.09 ccw(c3507.18,-1991.89) 3507.18,-1956.82
PC: P1.17 R61.1 | length 1442.6
  Top Layer w10: R61.1@3603.91,-1346.42 3669.79,-1412.3 3786.06,-1412.3 3824.19,-1450.42 3824.19,-1774.88 v2@3767.28,-1831.79 ; R61.1@3603.91,-1366.42 cw(c3603.91,-1414.71) 3638.06,-1380.57 ccw(c3603.91,-1414.71) R61.1@3603.91,-1366.42 ; R61.1@3603.91,-1356.42 cw(c3603.91,-1380.57) 3620.99,-1363.49 ccw(c3603.91,-1380.57) R61.1@3603.91,-1356.42 ; R61.1@3620.57,-1349.77 ccw(c3652.69,-1349.77) 3629.98,-1372.49 cw(c3652.69,-1349.77) R61.1@3620.57,-1349.77 ; v2@3767.66,-1822.43 ccw(c3767.66,-1800.74) 3782.99,-1816.08 cw(c3767.66,-1800.74) v2@3767.66,-1822.43 ; v2@3776.66,-1831.43 cw(c3798.43,-1831.43) 3783.03,-1816.03 ccw(c3798.43,-1831.43) v2@3776.66,-1831.43
  Bottom Layer w10: P1.17@3642.25,-1956.82 v2(3767.66,-1831.43) ; 3667.05,-1932.02 ccw(c3691.85,-1956.82) 3656.78,-1956.82 cw(c3691.85,-1956.82) 3667.05,-1932.02 ; 3667.05,-1932.02 cw(c3642.25,-1907.22) 3642.25,-1942.29 ccw(c3642.25,-1907.22) 3667.05,-1932.02 ; 3684.12,-1914.94 ccw(c3725.99,-1956.82) 3666.78,-1956.82 cw(c3725.99,-1956.82) 3684.12,-1914.94 ; 3684.12,-1914.94 cw(c3642.25,-1873.07) 3642.25,-1932.29 ccw(c3642.25,-1873.07) 3684.12,-1914.94 ; 3752.26,-1846.8 cw(c3767.66,-1862.2) 3767.66,-1840.43 ccw(c3767.66,-1862.2) 3752.26,-1846.8 ; 3752.3,-1846.76 ccw(c3736.97,-1831.43) 3758.66,-1831.43 cw(c3736.97,-1831.43) 3752.3,-1846.76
